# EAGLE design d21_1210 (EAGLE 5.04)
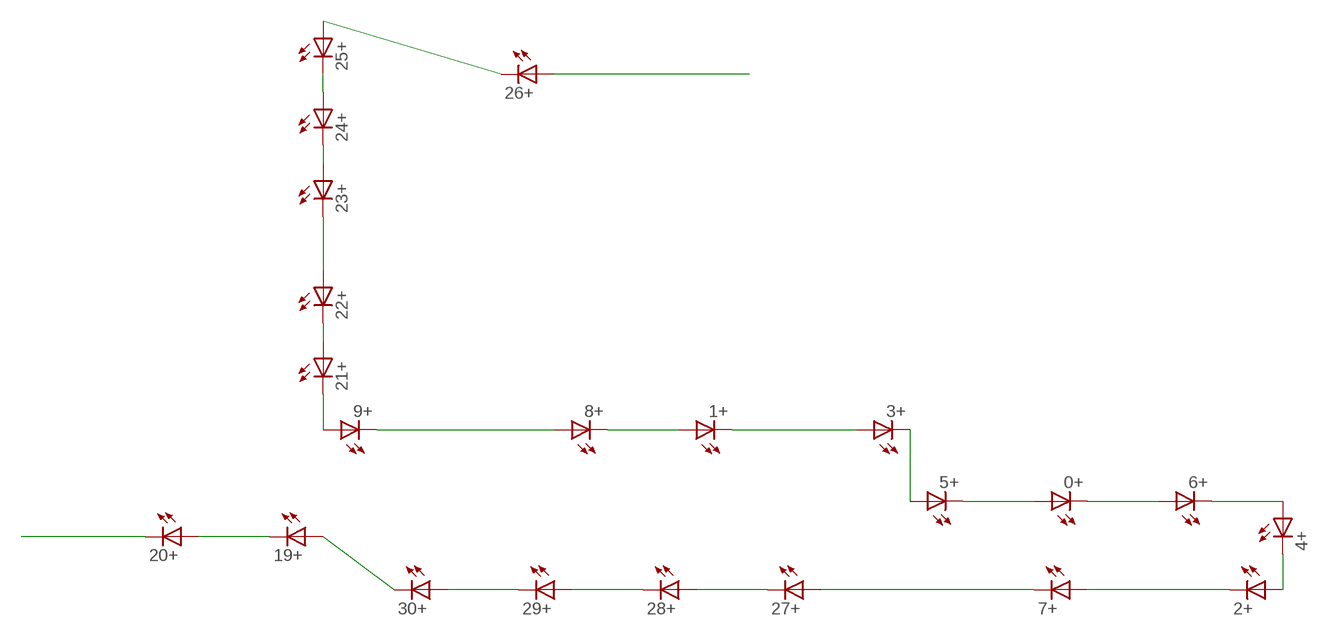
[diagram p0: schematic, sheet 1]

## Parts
0+  LED1210  [1210]
1+  LED1210  [1210]
2+  LED1210  [1210]
3+  LED1210  [1210]
4+  LED1210  [1210]
5+  LED1210  [1210]
6+  LED1210  [1210]
7+  LED1210  [1210]
8+  LED1210  [1210]
9+  LED1210  [1210]
19+  LED1210  [1210]
20+  LED1210  [1210]
21+  LED1210  [1210]
22+  LED1210  [1210]
23+  LED1210  [1210]
24+  LED1210  [1210]
25+  LED1210  [1210]
26+  LED1210  [1210]
27+  LED1210  [1210]
28+  LED1210  [1210]
29+  LED1210  [1210]
30+  LED1210  [1210]

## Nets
MINUS: 20+.P$2(C)
N$2: 19+.P$2(C) 20+.P$1(A)
N$4: 19+.P$1(A) 30+.P$2(C)
N$6: 8+.P$1(A) 9+.P$2(C)
N$7: 29+.P$2(C) 30+.P$1(A)
N$8: 28+.P$2(C) 29+.P$1(A)
N$9: 27+.P$2(C) 28+.P$1(A)
N$12: 2+.P$2(C) 7+.P$1(A)
N$13: 7+.P$2(C) 27+.P$1(A)
N$14: 2+.P$1(A) 4+.P$2(C)
N$15: 4+.P$1(A) 6+.P$2(C)
N$16: 0+.P$2(C) 6+.P$1(A)
N$17: 0+.P$1(A) 5+.P$2(C)
N$18: 3+.P$2(C) 5+.P$1(A)
N$19: 1+.P$2(C) 3+.P$1(A)
N$20: 1+.P$1(A) 8+.P$2(C)
N$23: 9+.P$1(A) 21+.P$2(C)
N$24: 21+.P$1(A) 22+.P$2(C)
N$25: 22+.P$1(A) 23+.P$2(C)
N$26: 24+.P$1(A) 25+.P$2(C)
N$27: 25+.P$1(A) 26+.P$2(C)
N$28: 23+.P$1(A) 24+.P$2(C)
PLUS: 26+.P$1(A)

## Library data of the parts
0+ 1+ 2+ 3+ 4+ 5+ 6+ 7+ 8+ 9+ 19+ 20+ 21+ 22+ 23+ 24+ 25+ 26+ 27+ 28+ 29+ 30+ = led(2):LED: LED

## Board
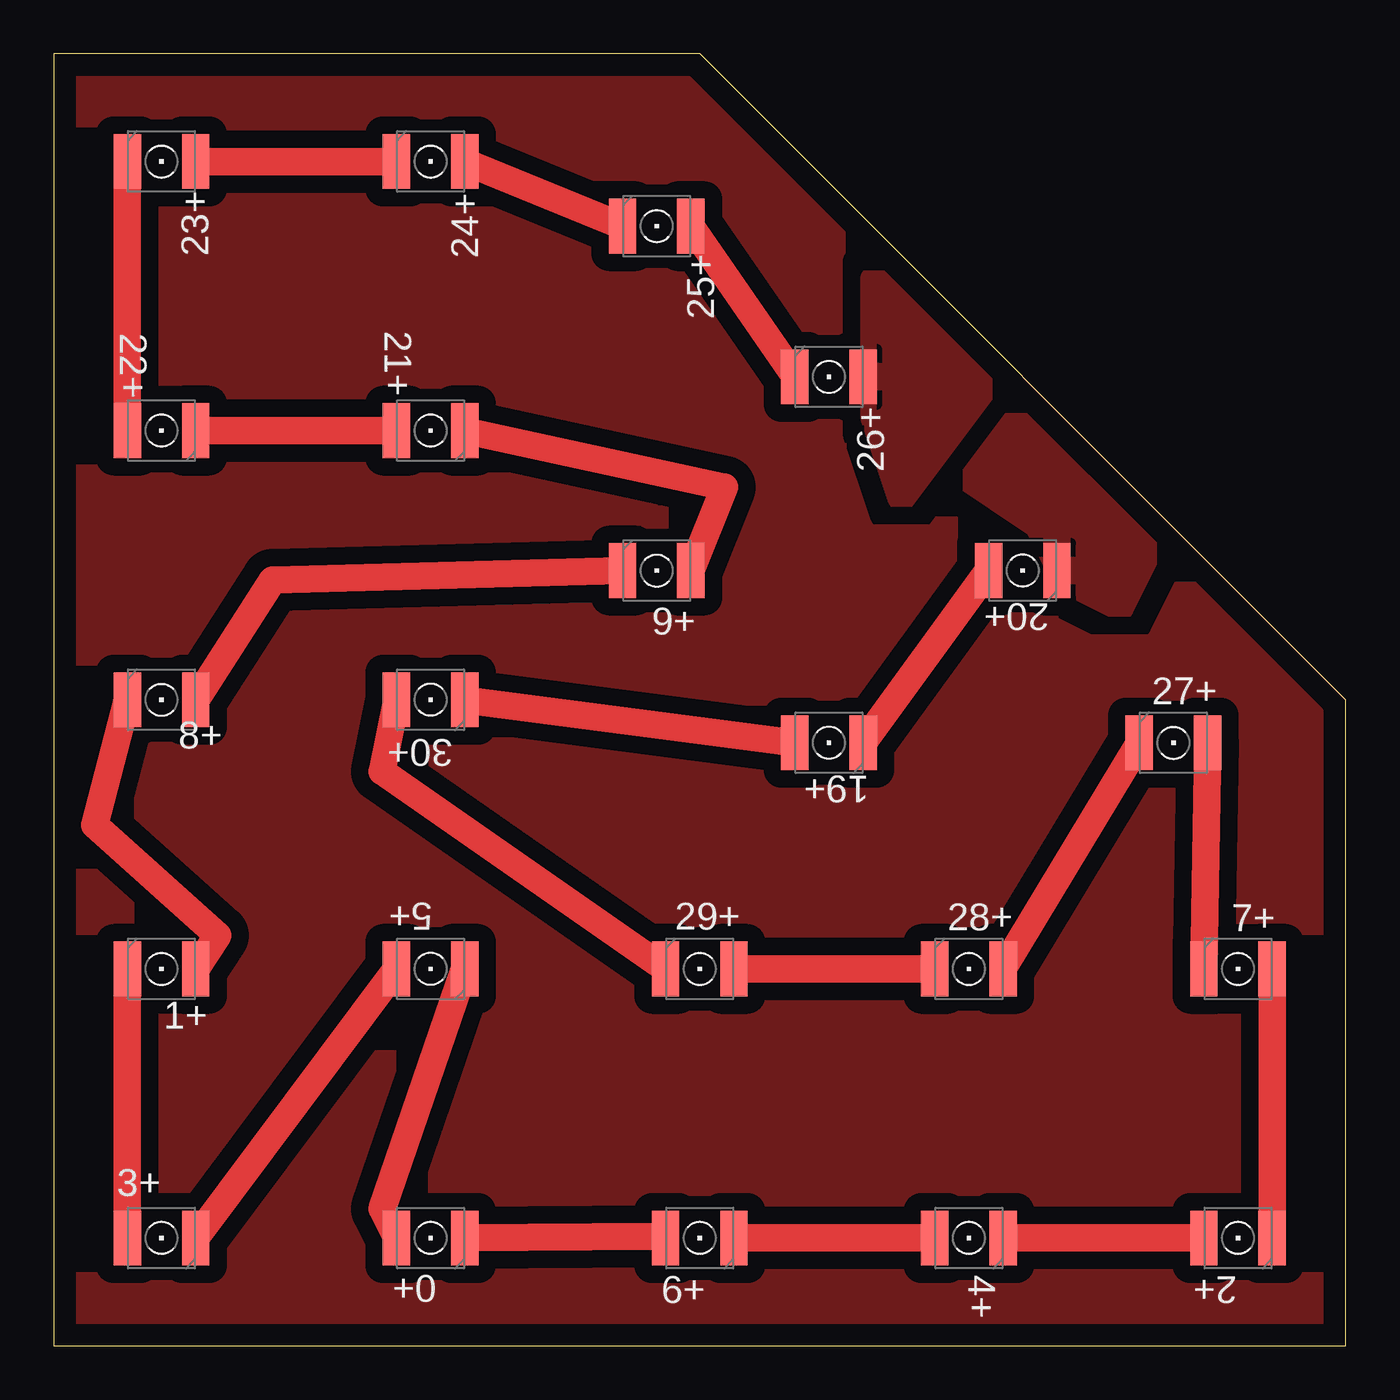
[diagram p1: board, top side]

Size 60 x 60 mm. Coordinates in mm from the lower left corner, seen from the top.
Outline: 0,0 60,0 60,30 30,60 0,60 0,0
Copper layers (1*16): Top 0.035mm / dielectric 1.5mm / Bottom 0.035mm
Design rules "default": minimum track width 10mil, minimum drill 24mil, track to track 8mil, track to pad 8mil, pad to pad 8mil, via to via 8mil, smd to smd 8mil, copper to edge 40mil, drill to drill 8mil, minimum pad ring 10mil, minimum via ring 8mil, stop-mask expansion 4mil, vias tented up to drill 0mil, thermal gap 10mil

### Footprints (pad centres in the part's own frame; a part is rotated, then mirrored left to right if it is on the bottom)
1210 = smd 1.27 x 2.54: P$1 1.587,0; P$2 -1.587,0

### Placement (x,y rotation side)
0+  17.5,5 180 top
1+  5,17.5 0 top
2+  55,5 180 top
3+  5,5 180 top
4+  42.5,5 180 top
5+  17.5,17.5 180 top
6+  30,5 180 top
7+  55,17.5 0 top
8+  5,30 0 top
9+  28,36 0 top
19+  36,28 180 top
20+  45,36 180 top
21+  17.5,42.5 180 top
22+  5,42.5 180 top
23+  5,55 0 top
24+  17.5,55 0 top
25+  28,52 0 top
26+  36,45 0 top
27+  52,28 0 top
28+  42.5,17.5 0 top
29+  30,17.5 0 top
30+  17.5,30 180 top

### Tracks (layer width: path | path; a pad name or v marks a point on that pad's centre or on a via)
MINUS
  pour Top (isolate 0.61, rank 2): 44.45,43.18 50.8,36.83 49.53,34.29 46.99,35.56 45.72,38.1 41.91,40.64
N$1
  pour Top (isolate 0.813, rank 3): 29.21,58.42 1.27,58.42 1.27,1.27 58.42,1.27 58.42,29.21
N$2
  Top 1.27: 19+.P$2 20+.P$1
N$4
  Top 1.27: 30+.P$2 19+.P$1
N$6
  Top 1.27: 9+.P$2 10.16,35.56 8+.P$1
N$7
  Top 1.27: 29+.P$2 15.24,26.67 30+.P$1
N$8
  Top 1.27: 29+.P$1 28+.P$2
N$9
  Top 1.27: 28+.P$1 27+.P$2
N$12
  Top 1.27: 2+.P$2 7+.P$1
N$13
  Top 1.27: 7+.P$2 27+.P$1
N$14
  Top 1.27: 4+.P$2 2+.P$1
N$15
  Top 1.27: 6+.P$2 4+.P$1
N$16
  Top 1.27: 0+.P$2 27.94,5.08 6+.P$1
N$17
  Top 1.27: 5+.P$2 15.24,6.35 0+.P$1
N$18
  Top 1.27: 3+.P$2 5+.P$1
N$19
  Top 1.27: 3+.P$1 1+.P$2
N$20
  Top 1.27: 8+.P$2 1.9,24.18 7.62,19.05 1+.P$1
N$23
  Top 1.27: 21+.P$2 31.14,39.88 9+.P$1
N$24
  Top 1.27: 22+.P$2 21+.P$1
N$25
  Top 1.27: 22+.P$1 23+.P$2
N$26
  Top 1.27: 24+.P$1 25+.P$2
N$27
  Top 1.27: 26+.P$2 25+.P$1
N$28
  Top 1.27: 23+.P$1 24+.P$2
PLUS
  pour Top (isolate 0.61): 38.1,49.53 43.18,44.45 39.37,39.37 38.1,43.18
